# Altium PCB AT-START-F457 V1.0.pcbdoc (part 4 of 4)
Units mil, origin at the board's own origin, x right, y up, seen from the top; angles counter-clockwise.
Board outline 11593.57 x 3554 mil, 2 copper layers (Top Layer, Bottom Layer); 196 components, 231 nets, 905 pads, 932 vias.
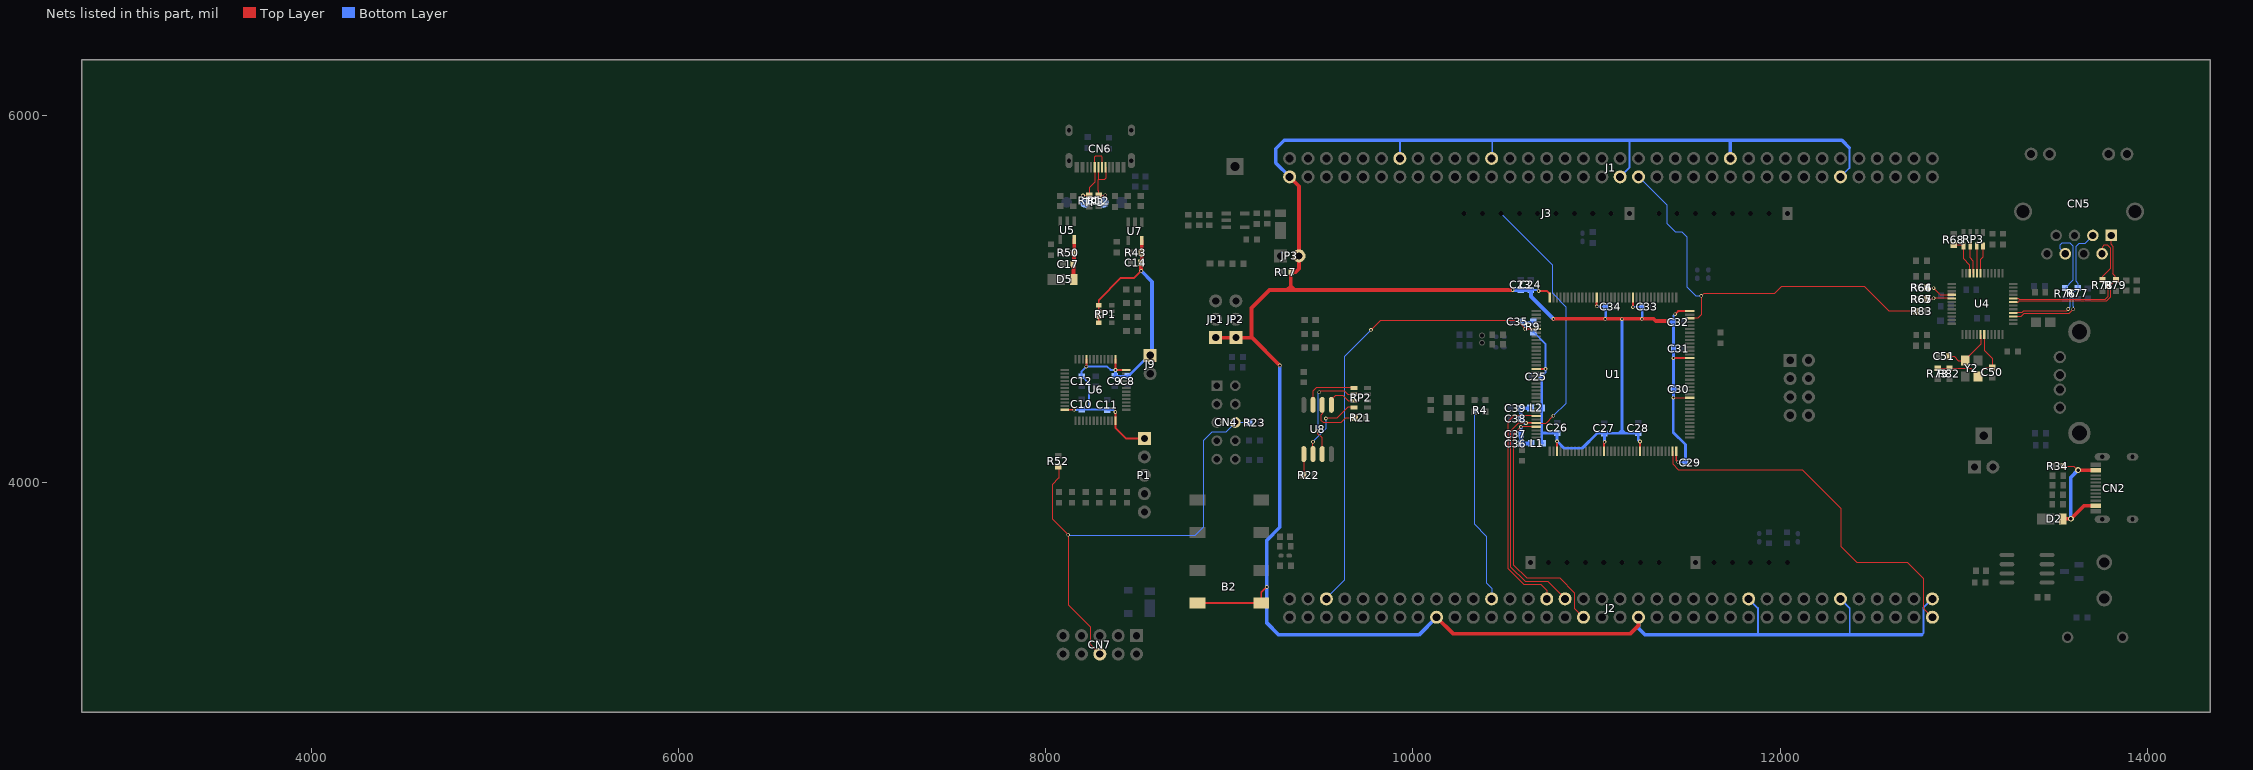
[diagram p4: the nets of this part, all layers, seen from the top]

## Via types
v1: diameter 19.7, hole 11.8, Top Layer to Bottom Layer, 489 vias
v2: diameter 19.68, hole 11.81, Top Layer to Bottom Layer, 425 vias
v3: diameter 31.5, hole 19.68, Top Layer to Bottom Layer, 18 vias

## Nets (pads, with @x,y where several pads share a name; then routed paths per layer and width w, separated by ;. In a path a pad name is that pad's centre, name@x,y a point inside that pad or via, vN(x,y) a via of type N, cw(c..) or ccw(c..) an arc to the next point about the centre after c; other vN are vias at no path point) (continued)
PH1_E: J2.24 R4.1 | length 1063.9
  Bottom Layer w6: R4.1@10335.06,4391.98 10335.06,3775.08 10401.16,3708.98 10401.16,3453.88 10429.16,3425.88 J2.24@10429.17,3367.08
PH2: J1.34 R83.1 U1.106 | length 2247.6
  Top Layer w6: U1.106@11508.56,4895.08 11551.03,4895.08 11570.59,4914.64 v2(11570.59,5017.3) 11583,5029.71 11969.32,5029.71 12005.63,5066.03 12461.73,5066.03 12594.18,4933.58 R83.1@12741.42,4933.58
  Bottom Layer w6: J1.34@11229.16,5665.68 11230.56,5665.68 11381.86,5514.38 11381.86,5413.88 11428.36,5367.38 11463.36,5367.38 11491.76,5338.98 11491.76,5065.69 11540.15,5017.3 v2(11570.59,5017.3)
PH3: J2.71 U1.71 | length 2046.3
  Top Layer w6: U1.71@11415.06,4171.68 11415.06,4101.68 11446.53,4070.32 12121.41,4070.32 12331.21,3860.53 12331.21,3654.73 12418.36,3567.58 12692.66,3567.58 12780.26,3479.88 12780.26,3316.08 J2.71@12829.17,3267.08
PH4: J2.30 U1.30 | length 1275.9
  Top Layer w6: U1.30@10671.86,4363.61 10548.56,4363.61 10515.57,4330.61 10515.57,3534.61 10603.57,3446.61 10695.57,3446.61 10729.17,3413.01 J2.30@10729.17,3367.08
QSPI1_CS: R22.2 U8.1 | length 116
  Top Layer w6: R22.2@9405.96,4039.98 9406.16,4040.18 U8.1@9406.16,4155.92
QSPI1_IO0: RP2.7 U8.5 | length 176.4
  Top Layer w6: U8.5@9556.16,4423.64 9556.16,4453.17 9579.6,4476.61 9617.57,4476.61 9648.91,4445.28 RP2.7@9680.35,4445.28
QSPI1_IO1: RP2.8 U8.2 | length 401.8
  Top Layer w5.98: U8.2@9456.16,4155.92 v2(9456.18,4222.41)
  Top Layer w6: v2(9526.59,4349.49) 9586.44,4349.49 9646.8,4409.85 RP2.8@9680.35,4409.85 ccw(c9680.11,4409.6) RP2.8@9680.11,4409.95
  Bottom Layer w6: v2(9456.18,4222.41) 9456.18,4223.22 9526.59,4293.63 v2(9526.59,4349.49)
QSPI1_IO2: RP2.6 U8.3 | length 552.2
  Top Layer w5.98: v2(9482.61,4281.14) 9482.61,4267.58 9506.16,4244.03 U8.3@9506.16,4155.92
  Top Layer w6: v2(9489.97,4492.3) 9498.29,4500.61 9625.57,4500.61 9645.47,4480.72 RP2.6@9680.35,4480.72
  Bottom Layer w5.98: v2(9482.61,4281.14) 9481.57,4282.18 9481.57,4483.9 v2(9489.97,4492.3)
QSPI1_IO3: RP2.5 U8.7 | length 307.3
  Top Layer w6: U8.7@9455.57,4424.23 ccw(c9456.18,4424.23) U8.7@9456.16,4423.64 ; U8.7@9455.56,4424.28 9455.56,4498.6 9473.1,4516.15 RP2.5@9680.35,4516.15
QSPI1_SCK: R21.2 U8.6 | length 287.1
  Top Layer w6: U8.6@9506.16,4423.64 9506.16,4374.87 9499.57,4368.29 9499.57,4340.61 9511.57,4328.61 9609.57,4328.61 9634.8,4353.85 R21.2@9685.52,4353.85
REF_CLK: R68.2 RP3.5 U4.22 | length 218.5
  Top Layer w6: R68.2@12946.16,5296.48 12992.56,5296.48 12999.96,5289.18 12999.96,5218.28 13033.36,5184.88 U4.22@13033.36,5141.28
RX+: CN5.3 R77.2 U4.3 | length 822.4
  Top Layer w6: U4.3@13269.53,4905.07 13312.69,4905.07 13330.49,4922.87 13575.43,4922.87 v2(13597.03,4944.47)
  Bottom Layer w6: v2(13597.03,4944.47) 13597.03,4960.96 13593.54,4964.44 13593.54,5031.86 13622.25,5060.58 13622.25,5085.93 13609.51,5098.66 13609.51,5285.42 13625.67,5301.58 13658.26,5301.58 CN5.3@13703.26,5346.48
RX-: CN5.6 R76.2 U4.4 | length 829.2
  Top Layer w6: U4.4@13269.53,4924.76 13315.43,4924.76 13325.52,4934.85 13558.95,4934.85 v2(13569.76,4945.66)
  Bottom Layer w6: R76.2@13552.21,5059.63 13552.58,5059.63 13597.51,5104.56 13597.51,5287.18 13580.75,5303.94 13533.87,5303.94 13523.23,5293.3 13523.23,5276.71 CN5.6@13553.46,5246.48 ; R76.2@13552.26,5057.48 13581.54,5028.2 13581.54,4957.44 v2(13569.76,4945.66)
RXD0: R65.2 R67.2 U4.29 | length 173.3
  Top Layer w6: R65.2@12800.74,4998.98 12828.39,4998.98 12832.9,5003.5 U4.29@12934.89,5003.5
  Bottom Layer w6: R67.2@12801.14,4998.59 12830.58,4998.59 v2(12836.09,5004.1)
RXD1: R64.2 R66.2 U4.28 | length 186.7
  Top Layer w6: R64.2@12800.74,5062.81 12833.73,5062.81 12873.36,5023.18 U4.28@12934.89,5023.18
  Bottom Layer w6: R66.2@12800.51,5060.32 12835.3,5060.32 v2(12836.27,5059.35)
SWO: CN4.6 CN7.6 R23.1 R52.2 | length 2661.3
  Top Layer w6: 8070.23,4023.63 8035.17,3988.57 8035.17,3804.01 v2(8122.8,3716.38) 8124.77,3714.41 8124.77,3332.21 8245.21,3211.77 8245.21,3116.85 CN7.6@8295.43,3066.63 ; 8070.26,4023.68 R52.2@8070.26,4081.58
  Bottom Layer w6: v2(8122.8,3716.38) 8124.56,3714.61 8815.89,3714.61 8860.26,3758.98 8860.26,4231.98 8906.26,4277.98 8984.36,4277.98 9034.56,4328.18 9112.76,4328.18 R23.1@9112.76,4325.98
TX+: CN5.1 R79.2 U4.7 | length 899.7
  Top Layer w6: U4.7@13269.59,4983.81 13295.94,4983.81 13299.69,4987.56 13775.42,4987.56 13798.24,5010.38 13798.24,5073.37 13826.16,5101.38 13826.16,5123.08 13812.82,5136.48 13812.82,5287.18 13799.82,5300.18 13799.82,5334.47 13803.46,5338.12 CN5.1@13803.46,5346.48
TX-: CN5.2 R78.2 U4.8 | length 906.6
  Top Layer w6: U4.8@13269.53,5003.5 13298.2,5003.5 13302.15,4999.56 13770.45,4999.56 13786.24,5015.35 13786.24,5069.2 R78.2@13755.66,5099.78 ; CN5.2@13753.46,5246.48 13753.46,5283.19 13761.99,5291.72 13784.84,5291.72 13800.82,5275.75 13800.82,5168.62 13756.08,5123.88 R78.2@13756.08,5103.9
TXD0: RP3.7 U4.20 | length 148.7
  Top Layer w6: RP3.7@13070.76,5289.18 13072.66,5287.28 U4.20@13072.68,5141.29
TXD1: RP3.8 U4.19 | length 153.7
  Top Layer w6: U4.19@13092.37,5141.29 13092.36,5216.08 13106.26,5229.98 RP3.8@13106.26,5289.18
TXEN: RP3.6 U4.21 | length 155.2
  Top Layer w6: RP3.6@13035.36,5289.18 13035.36,5224.88 13052.96,5207.18 U4.21@13053,5141.29
USBM: CN6.A7 CN6.B7 R12.1 TP3.2 | length 334.9
  Top Layer w6: CN6.A7@8287.41,5717.9 8287.41,5649.64 ; v2(8324.77,5565.01) 8324.24,5564.48 R12.1@8290.08,5564.48 8290.08,5586.36 8287.41,5589.03 8287.41,5649.64 ; CN6.B7@8326.71,5717.9 8326.71,5657.74 8318.61,5649.64 8287.41,5649.64
  Bottom Layer w6: TP3.2@8314.58,5526.61 8324.77,5536.8 v2(8324.77,5565.01)
USBP: CN6.A6 CN6.B6 R11.1 TP3.3 | length 398.8
  Top Layer w6: v2(8203.57,5563.81) 8203.69,5563.69 R11.1@8238.07,5563.69 8238.07,5607.32 8267.71,5636.95 CN6.B6@8267.71,5717.9 8267.71,5774.07 8272.74,5779.1 8302.29,5779.1 8307.01,5774.39 CN6.A6@8307.01,5717.9
  Bottom Layer w6: v2(8203.57,5563.81) 8203.57,5537.62 TP3.3@8214.58,5526.61
VBAT: C35.1 J2.6 R9.1 U1.6 | length 2722.4
  Top Layer w6: v2(9772.21,4831.97) 9821.36,4881.18 10566.96,4881.18 v2(10611.21,4836.97) 10612.06,4836.08 U1.6@10671.86,4836.08
  Top Layer w10: v2(10611.21,4836.97) U1.6@10671.86,4836.08
  Bottom Layer w6: J2.6@9529.17,3367.08 9529.16,3370.98 9628.26,3470.08 9628.26,4687.98 v2(9772.21,4831.97) ; C35.1@10598.77,4875.97 10654.76,4875.98 R9.1@10655.26,4875.48
  Bottom Layer w10: v2(10611.21,4836.97) 10611.16,4863.48 10598.66,4875.98 R9.1@10655.16,4875.48
VBUS: CN2.A4B9 CN2.B4A9 D2.2 R34.2 | length 676.4
  Top Layer w6: R34.2@13542.43,4090.63 13600.62,4090.63 v3(13622.88,4068.37)
  Top Layer w20: D2.2@13539.49,3802.96 13539.6,3803.07 v3(13583.83,3803.07) 13654.99,3874.23 CN2.A4B9@13718.81,3874.23 ; v3(13622.88,4068.37) 13624.02,4067.23 CN2.B4A9@13718.81,4067.23
  Bottom Layer w20: v3(13583.83,3803.07) 13583.83,4029.31 v3(13622.88,4068.37)
VCC: C8.2 C9.2 C10.2 C11.2 C12.2 C14.2 J9.1 P1.1 R43.1 RP1.1 RP1.2 RP1.3 RP1.4 U6.1 U6.9 U6.24 U6.36 U6.48 U7.5 | length 2489.8
  Top Layer w10: U6.24@8104.56,4397.08 8154.68,4397.08 v2(8155.18,4396.59) ; v2(8221.57,4631.81) 8222.69,4632.94 U6.9@8222.69,4672.63 ; RP1.4@8289.33,4870.97 RP1.3@8289.33,4902.46 RP1.2@8289.33,4933.96 RP1.1@8289.33,4965.45 8289.33,4994.38 8409.97,5115.01 8482.37,5115.01 v2(8520.77,5153.41) ; v2(8379.97,4385.01) 8380.17,4384.81 U6.36@8380.17,4337.98 8380.16,4298.64 8438.61,4240.18 P1.1@8538.16,4240.18 ; U6.1@8380.16,4672.68 8380.16,4632.38 8380.46,4632.08 v2(8380.46,4613.78) 8400.16,4613.78 8400.36,4613.58 U6.48@8439.26,4613.58
  Top Layer w20: v2(8520.77,5153.41) 8519.37,5154.82 C14.2@8519.37,5197.16 8524.34,5202.13 U7.5@8524.34,5318.39
  Bottom Layer w6: C10.2@8196.77,4398.65 C10.2@8198.74,4398.65
  Bottom Layer w10: v2(8155.18,4396.59) 8170.98,4396.59 8173.05,4398.65 C10.2@8196.77,4398.65 ; C10.2@8198.74,4398.65 8235.87,4398.65 ; v2(8379.97,4385.01) 8369.13,4395.85 C11.2@8335.17,4395.85 8332.01,4399.01 8299.97,4399.01 8299.61,4398.65 8235.87,4398.65 ; v2(8380.46,4613.78) 8353.6,4613.78 8335.57,4631.81 v2(8221.57,4631.81) 8196.37,4606.61 C12.2@8196.37,4579.77 8198.34,4579.77 8235.57,4542.54 8235.57,4398.95 8235.87,4398.65
  Bottom Layer w15: v2(8380.46,4613.78) 8380.46,4584.26 C9.2@8376.37,4580.17 8445.57,4580.17 C8.2@8446.37,4580.97 8450.73,4580.97 8563.33,4693.58 J9.1@8569.46,4693.58
  Bottom Layer w20: v2(8520.77,5153.41) 8579.57,5094.61 8579.57,4703.69 J9.1@8569.46,4693.58
VCC3.5V: C17.2 D5.2 R50.1 U5.5 | length 217
  Top Layer w20: D5.2@8152.36,5107.05 U5.5@8155.56,5324.05
VDD: B2.1 B2.3 C23.1 C24.1 C25.1 C26.1 C27.1 C28.1 C29.1 C30.1 C31.1 C32.1 C33.1 C34.1 J1.12 J1.23 J1.36 J1.49 J1.59 J1.72 J2.17 J2.39 J2.52 J2.62 J2.72 JP1.1 JP2.1 JP3.2 L1.1 L2.1 R9.2 R17.2 U1.17 U1.39 U1.52 U1.62 U1.72 U1.84 U1.95 U1.108 U1.121 U1.131 U1.144 | length 18151.8
  Top Layer w6: v2(11001.21,4959.97) 11001.16,5007.88 U1.131@11001.66,5008.28 ; v2@11198.26,4955.98 11198.26,5007.98 U1.121@11198.46,5008.28 ; v2(11237.21,4223.97) 11237.86,4223.28 U1.62@11237.86,4171.68 ; v2(11419.26,4462.98) 11420.26,4461.98 11508.36,4461.98 U1.84@11508.56,4461.98
  Top Layer w10: B2.3@8828.03,3344.39 B2.1@9174.49,3344.39 9174.46,3402.18 v2@9204.26,3431.98 ; U1.17@10671.86,4619.52 v2(10722.29,4619.56) ; v2(10685.21,5043.97) 10730.21,5043.97 10745.68,5028.51 U1.144@10745.68,5008.31 ; U1.39@10785.06,4171.68 v2(10785.09,4224.97) ; v2(11001.21,4959.97) U1.131@11001.66,5008.28 ; U1.52@11040.96,4171.68 11040.96,4218.78 v2@11044.26,4221.98 ; v2@11198.26,4955.98 U1.121@11198.46,5008.28 ; v2(11237.21,4223.97) U1.62@11237.86,4171.68 ; v2(11419.26,4678.58) U1.95@11508.48,4678.57 ; v2(11428.26,4917.98) 11444.76,4934.48 U1.108@11508.48,4934.48 ; U1.72@11434.66,4171.68 11434.66,4121.17 v2(11444.88,4110.95) ; U1.84@11508.36,4461.98 U1.84@11508.46,4462.08
  Top Layer w20: JP1.1@8926.26,4789.98 9036.26,4789.98 9121.56,4789.98 ; v2(9275.08,4638.41) 9123.56,4789.98 9121.56,4789.98 ; J1.72@9329.18,5665.65 9380.21,5614.62 JP3.2@9380.21,5234.97 ; JP3.2@9380.21,5234.97 9380.16,5164.98 9362.26,5146.98 9335.76,5146.98 9335.86,5070.28 ; J2.17@10129.17,3267.08 10218.28,3177.97 11185.21,3177.97 11229.18,3221.93 J2.39@11229.17,3267.08 ; v2@10543.26,5048.98 9357.26,5048.98 ; v2(10765.65,4891.76) 10765.87,4891.98 v2@11048.26,4891.98 ; v2(11048.21,4891.97) v2(11247.21,4891.97) 11312.67,4891.97 11323.77,4880.87 v1(11387.81,4880.87) ; 9121.56,4789.98 9121.56,4951.28 9219.26,5048.98 9315.36,5048.98 ; 9315.36,5048.98 9335.86,5070.28 ; 9315.36,5048.98 9357.26,5048.98 ; 9335.86,5070.28 9357.26,5048.98
  Bottom Layer w6: v2(11001.21,4959.97) v2@11002.16,4958.98 ; C32.1@11418.02,4872.73 C32.1@11418.02,4879.87
  Bottom Layer w10: J1.59@9929.18,5765.65 9929.18,5862.18 9931.37,5864.38 ; J1.49@10429.18,5765.65 10432.2,5768.67 10432.2,5864.38 ; C24.1@10643.21,5049.41 10679.77,5049.41 v2(10685.21,5043.97) ; R9.2@10655.16,4820.48 10658.06,4820.48 10722.26,4756.28 v2(10722.29,4619.56) ; C25.1@10700.77,4576.97 10701.87,4578.07 10722.29,4598.48 v2(10722.29,4619.56) ; v2@11001.16,4958.98 11002.16,4958.98 C34.1@11050.76,4958.98 ; J1.36@11129.18,5665.65 11179.27,5715.74 11179.27,5864.38 ; v2@11198.26,4955.98 11200.16,4957.98 C33.1@11249.65,4957.97 ; C32.1@11419.02,4880.87 11419.02,4908.74 v2(11428.26,4917.98) ; C30.1@11420.01,4508.61 11422.36,4510.97 C30.1@11431.65,4510.97 ; v2(11444.88,4110.95) 11482.5,4110.95 C29.1@11484.44,4109.02 ; J2.52@11829.17,3367.08 11879.21,3317.04 11879.21,3170.98 ; J2.62@12329.17,3367.08 12379.21,3317.04 12379.21,3170.98 ; J1.12@12329.18,5665.65 12377.21,5713.68 12377.21,5823.97 ; 12771.26,3170.98 12780.26,3179.98 12780.26,3318.08 J2.72@12829.17,3367.08
  Bottom Layer w15: C25.1@10701.87,4578.07 L2.1@10701.88,4406.61 10701.87,4270.79 10701.56,4270.48 ; L1.1@10705.57,4214.98 10701.56,4218.98 10701.56,4270.48 ; C27.1@11043.26,4268.48 11003.66,4268.48 10922.88,4187.61 10823.59,4187.61 10785.06,4226.01 10785.26,4270.48 10701.56,4270.48 ; C27.1@11043.26,4269.48 11122.36,4269.48 ; v2@11044.26,4221.98 C27.1@11044.26,4267.48 ; v2@11048.26,4891.98 11050.76,4891.98 C34.1@11050.76,4958.98 ; 11138.66,4285.98 11122.36,4269.48 ; v2(11138.7,4890.97) 11138.7,4285.98 11155.2,4269.48 ; v2@11237.26,4223.98 11228.26,4232.98 11228.26,4269.48 11155.2,4269.48 ; v2(11247.21,4891.97) 11249.66,4894.48 C33.1@11249.65,4957.97 ; v2@11418.01,4454.73 11418.01,4273.17 11484.44,4206.75 C29.1@11484.44,4109.02 ; v2@11420.01,4462.77 C30.1@11420.01,4508.61 C32.1@11420.01,4872.61 ; 11122.36,4269.48 11155.2,4269.48
  Bottom Layer w20: v2(9275.08,4638.41) 9275.08,3756.83 9205.26,3687.01 9205.26,3235.98 9270.26,3170.98 10033.06,3170.98 J2.17@10129.17,3267.08 ; J1.72@9329.16,5665.68 9253.46,5741.38 9253.46,5818.28 9299.56,5864.38 9931.37,5864.38 10432.2,5864.38 11179.27,5864.38 11729.18,5864.38 ; v2(10543.21,5048.97) 10587.57,5048.97 10642.77,5048.97 C24.1@10643.21,5049.41 10643.21,5014.2 v2(10765.65,4891.76) ; J2.39@11229.17,3267.08 11231.21,3265.04 11231.21,3204.97 11265.2,3170.98 11879.21,3170.98 12379.21,3170.98 12771.26,3170.98 ; v1(11387.81,4880.87) C32.1@11418.01,4880.87 ; J1.23@11729.18,5765.65 11729.18,5864.38 ; 12377.26,5823.98 12336.76,5864.38 11729.18,5864.38
  other v2: 9204.21,3431.97 11044.21,4221.97 11198.21,4955.97
VDDA: C36.1 C37.1 J2.33 L1.2 U1.33 | length 1590.7
  Top Layer w6: U1.33@10671.86,4304.56 10588.86,4304.58 10548.16,4263.88 10548.16,3552.03 10619.2,3480.98 10799.46,3480.98 10880.26,3400.18 10880.26,3316.08 J2.33@10929.17,3267.08
  Bottom Layer w6: v2@10588.26,4303.98 10588.66,4303.48 C37.1@10588.66,4264.98 ; L1.2@10642.86,4212.98 L1.2@10644.94,4214.98
  Bottom Layer w20: v2@10588.26,4303.98 10588.66,4264.98 10588.66,4212.98 L1.2@10642.86,4212.98 ; L1.2@10642.96,4212.98 L1.2@10644.96,4214.98
  other v2: 10588.21,4303.97
VREF+: C38.1 C39.1 J2.32 J3.8 L2.2 U1.32 | length 2918.4
  Top Layer w6: v2(10616.21,4324.97) 10671.16,4324.98 U1.32@10671.86,4324.24 ; v2@10765.66,4363.98 10725.86,4324.18 U1.32@10671.86,4324.24 ; J2.32@10829.17,3367.08 10734.26,3461.98 10612.2,3461.98 10531.56,3542.63 10531.56,4281.28 10574.46,4324.18 U1.32@10671.86,4324.24
  Bottom Layer w6: J3.8@10479.86,5465.98 10758.26,5187.58 10758.26,5033.65 10832.57,4959.34 10832.57,4430.89 v2@10765.66,4363.98 ; C39.1@10586.77,4404.97 10586.76,4348.98 C38.1@10587.13,4348.61 ; L2.2@10639.53,4404.98 L2.2@10641.25,4406.61
  Bottom Layer w20: v2(10616.21,4324.97) 10610.76,4324.98 C38.1@10587.13,4348.61 10587.12,4404.62 C39.1@10586.77,4404.97 L2.2@10639.53,4404.98 ; L2.2@10639.63,4404.98 L2.2@10641.27,4406.61
  other v2: 10765.63,4364
XT1: C50.1 R73.2 R82.1 U4.43 Y2.1 | length 539.8
  Top Layer w6: R73.2@12858.77,4623.47 12921.57,4623.47 R82.1@12922.37,4622.67 13037.11,4622.67 13072.02,4587.76 Y2.1@13072.02,4583.64 ; Y2.1@13077.62,4578.5 13077.16,4578.5 Y2.1@13072.02,4583.64 ; U4.43@13112.05,4806.65 13112.05,4721.74 13156.37,4677.41 C50.1@13156.37,4627.77 13121.93,4627.77 13077.8,4583.64 Y2.1@13072.02,4583.64
XT2: C51.1 U4.42 Y2.3 | length 273.7
  Top Layer w6: C51.1@12920.73,4688.21 12948.37,4688.21 12971.46,4665.12 Y2.3@13008.72,4665.12 13008.72,4669.36 13092.37,4753.01 U4.42@13092.37,4806.65
pads on no net: CN2.A8 CN2.B8 CN5.7 CN6.A8 CN6.B8 J4.1 J4.8 U4.11 U4.14 U4.16 U4.17 U4.18 U4.26 U4.27 U4.34 U4.35 U4.38 U4.39 U4.45 U6.2 U6.3 U6.4 U6.5 U6.6 U6.14 U6.15 U6.16 U6.17 U6.18 U6.21 U6.22 U6.29 U6.38 U6.41 U6.42 U6.43 U6.45 U6.46

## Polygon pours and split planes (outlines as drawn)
GND on Top Layer (solid, remove dead copper, pour order 0): 7929.57,6050.61 14093.57,6050.61 14093.57,3000.61 7929.57,3000.61
GND on Bottom Layer (solid, remove dead copper, pour order 2): 7904.5,6054 14034.5,6054 14034.5,3000 7904.5,3000

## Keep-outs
Top Layer:
  region: 8093.57,6044.61 8503.57,6044.61 8503.57,5692.61 8093.57,5692.61
  region: 11000.57,5092.61 11028.57,5092.61 11028.57,5089.61 11000.57,5089.61
  region: 8427.33,4456.25 8427.33,4435.51 8454.37,4435.51 8454.37,4456.25 8427.4,4456.25
  region: 13170.22,4819.74 13170.22,4788.69 13192.59,4788.69 13192.59,4819.72 13170.85,4819.72
  region: 13239.55,4969.43 13239.55,4938.7 13245.85,4938.7 13311.65,4938.7 13311.65,4944.48 13311.65,4969.43 13240.73,4969.43
  region: 9705.37,4533.67 9727.83,4533.67 9727.83,4528.15 9705.37,4528.15
Bottom Layer:
  region: 14037.21,5173.97 13269.21,5173.97 13269.21,6033.97 14037.21,6033.97
Board Outline Layer:
  circle w1: c12139.81,4865.97 r62.99
  circle w10: c12139.81,4865.97 r62.99
  circle w1: c10139.81,5465.96 r62.99
  circle w10: c10139.81,5465.96 r62.99
  circle w1: c10089.81,3565.97 r62.99
  circle w10: c10089.81,3565.97 r62.99
  circle w1: c8818.39,5874.63 r62.99
  circle w10: c8818.39,5874.63 r62.99
  circle w1: c8818.39,3158.09 r62.99
  circle w10: c8818.39,3158.09 r62.99
  circle w1: c13109.73,3158.09 r62.99
  circle w10: c13109.73,3158.09 r62.99
  circle w1: c13109.73,5874.63 r62.99
  circle w10: c13109.73,5874.63 r62.99
  region: 14037.21,5161.97 13269.21,5161.97 13269.21,6033.97 14037.21,6033.97
  lines w8: 8582.96,6032.21 cw(c8582.96,5953.47) 8661.7,5953.47 8661.7,5631.63 8701.21,5631.63 8701.21,5953.46 cw(c8779.95,5953.46) 8779.95,6032.2 ; 8583.39,3000.61 ccw(c8583.39,3079.35) 8662.13,3079.35 8662.16,3079.38 8662.16,3518.58 8700.96,3518.58 8700.96,3079.38 8700.96,3079.35 ccw(c8779.7,3079.35) 8779.7,3000.61 ; 8661.66,5546.58 8661.66,5553.58 8701.26,5553.58 8701.26,5546.58 8701.22,5546.58 8701.22,5224.75 8701.22,4903.97 ; 8661.7,5546.59 8661.7,5224.75 8661.7,4904.49 ; 8661.7,4904.49 8662.57,4903.61 ; 8661.7,4904.49 ccw(c8662.57,4904.49) 8662.57,4903.61 ; 8662.57,4903.61 8700.86,4903.61 ; 8700.86,4903.61 8701.22,4903.97 ; 8700.86,4903.61 ccw(c8700.86,4903.97) 8701.22,4903.97 ; 8661.57,3606.61 8661.57,3698.61 8701.57,3698.61 8701.57,3606.61 8661.57,3606.61 ; 8661.57,3810.61 8661.57,4809.61 8661.57,4825.61 8680.57,4825.61 8700.57,4825.61 8700.57,3825.61 8700.57,3810.61 8699.57,3810.61 8661.57,3810.61
  lines w10: 7929.57,3079.35 ccw(c8008.31,3079.35) 8008.31,3000.61 13953.19,3000.61 ccw(c13953.19,3079.35) 14031.93,3079.35 14031.93,5953.37 ccw(c13953.19,5953.37) 13953.19,6032.11 8008.31,6032.11 ccw(c8008.31,5953.37) 7929.57,5953.37 7929.57,3079.35

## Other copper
Top Layer:
  drawing of 1092 lines, arcs and shapes, not listed
Bottom Layer:
  drawing of 655 lines, arcs and shapes, not listed

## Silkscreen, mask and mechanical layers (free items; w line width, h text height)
Top Silkscreen Layer:
  region: 12061.06,5334.85 12023.06,5334.85 12043.06,5354.85 12063.06,5334.85
  region: 11922.7,5352.85 11960.7,5352.85 11940.7,5332.85 11920.7,5352.85
  lines w6: 8141.98,3304.61 8141.98,3603.61 ; 8238.38,3304.61 8238.38,3603.61 ; 8334.77,3303.61 8334.77,3603.61 ; 8431.17,3309.61 8431.17,3603.61
  lines w8: 8243,3218.63 8243,3258.63 8343,3258.63 8343,3217.63 ; 8533.55,3272.63 8496.55,3235.63 8457.55,3274.63 8533.55,3274.63 ; 8842.11,4558.1 8875.56,4528.18 8841.33,4499.39 8841.33,4557.7 8842.9,4557.31 ; 8881.91,4376.46 8859.05,4376.46 8859.05,4277.18 8882.06,4277.18 8882.06,4278.37
  lines w10: 10652.7,5212.76 12068.4,5212.76 ; 10942.92,3858.17 11395.93,3858.17 ; 11541.16,3858.17 12101.16,3858.17
  text "143" at 9294.03,5925.4 h53.08
  text "133" at 9778.67,5925.4 h53.08
  text "123" at 10283.4,5925.34 h53.08
  text "113" at 10800.72,5925.42 h53.08
  text "103" at 11286.94,5925.43 h53.08
  text "93" at 11797.25,5925.41 h53.08
  text "83" at 12303.16,5925.43 h53.08
  text "73" at 12798.04,5925.41 h53.08
  text "D8" at 12614.84,5826.64 h53.08 r45
  text "B12" at 12814.13,5827.4 h53.08 r45
  text "E0" at 9430.12,5824.52 h53.08 r45
  text "D7" at 10318.9,5825.28 h53.08 r45
  text "D12" at 12415.09,5824.62 h53.08 r45
  text "D10" at 12514.89,5825.31 h53.08 r45
  text "B14" at 12714.99,5825.34 h53.08 r45
  text "B8" at 9526.51,5823.55 h53.08 r45
  text "B3" at 9826.63,5823.87 h53.08 r45
  text "D1" at 10725.32,5823.89 h53.08 r45
  text "A14" at 11016.9,5823.66 h53.08 r45
  text "A13" at 11214.65,5823.89 h53.08 r45
  text "A11*" at 11319.48,5823.92 h53.08 r45
  text "A9" at 11426.06,5823.63 h53.08 r45
  text "D14" at 12219.86,5823.66 h53.08 r45
  text "B5" at 9727.99,5823.17 h53.08 r45
  text "D5" at 10530.89,5822.21 h53.08 r45
  text "D3" at 10626.84,5822.42 h53.08 r45
  text "B7" at 9625.2,5820.13 h53.08 r45
  text "G10" at 10218.23,5820.36 h53.08 r45
  text "G8" at 11820.07,5819.93 h53.08 r45
  text "G12" at 10118.32,5818.91 h53.08 r45
  text "GND" at 11114.44,5819.33 h53.08 r45
  text "G2" at 12119.89,5819.18 h53.08 r45
  text "GND" at 9334.9,5817.96 h53.08 r45
  text "C7" at 11625.79,5817.66 h53.08 r45
  text "G6" at 11922.73,5818.3 h53.08 r45
  text "C12" at 10818.19,5816.54 h53.08 r45
  text "C9" at 11519.64,5817.36 h53.08 r45
  text "G4" at 12017.33,5817.43 h53.08 r45
  text "GND" at 12312.34,5817.24 h53.08 r45
  text "G14" at 10017.34,5816.49 h53.08 r45
  text "VDD" at 10418.16,5815.77 h53.08 r45
  text "C10" at 10920.36,5815.82 h53.08 r45
  text "VDD" at 11710.07,5815.74 h53.08 r45
  text "VDD" at 9913.84,5812.5 h53.08 r45
  text "GND" at 8977.64,5808.6 h61.93
  text "Ethernet" at 13283.52,5621.66 h82.58 r90
  text "B6" at 9742.77,5537.36 h53.08 r45
  text "B9" at 9540.12,5533.83 h53.08 r45
  text "E1" at 9435.76,5530.95 h53.08 r45
  text "B4" at 9835.99,5531.15 h53.08 r45
  text "D6" at 10432.23,5530.95 h53.08 r45
  text "G11" at 10230.83,5527.56 h53.08 r45
  text "D4" at 10637.55,5524.86 h53.08 r45
  text "G13" at 10109.58,5524.31 h53.08 r30
  text "G9" at 10324.42,5524.4 h53.08 r45
  text "D0" at 10838.83,5524.06 h53.08 r45
  text "G5" at 12031.09,5523.75 h53.08 r45
  text "G3" at 12133.79,5523.58 h53.08 r45
  text "D2" at 10739.23,5522.71 h53.08 r45
  text "H2" at 11232.67,5523.43 h53.08 r45
  text "C6" at 11737.72,5522.99 h53.08 r45
  text "G7" at 11932.92,5522.76 h53.08 r45
  text "A8*" at 11533.03,5521.69 h53.08 r45
  text "C8" at 11633,5522.25 h53.08 r45
  text "C11" at 10934.3,5519.65 h53.08 r45
  text "A10" at 11429.72,5519.73 h53.08 r45
  text "G15" at 9928.83,5517.95 h53.08 r45
  text "D11" at 12532.33,5516.61 h53.08 r45
  text "A15" at 11025.3,5515.46 h53.08 r45
  text "D15" at 12226.07,5515 h53.08 r45
  text "D9" at 12634.99,5513.64 h53.08 r45
  text "VDD" at 9317.08,5512.52 h53.08 r45
  text "GND" at 11820.45,5513.47 h53.08 r45
  text "GND" at 10021.29,5511.87 h53.08 r45
  text "GND" at 10526.54,5511.97 h53.08 r45
  text "A12*" at 11322.84,5511.95 h53.08 r45
  text "B15" at 12734.91,5511.09 h53.08 r45
  text "D13" at 12427.78,5509.01 h53.08 r45
  text "B13" at 12832.59,5509.41 h53.08 r45
  text "VDD" at 11121.07,5507.7 h53.08 r45
  text "VDD" at 12323.24,5503.68 h53.08 r45
  text "BOOT0" at 9597.79,5485.43 h44.24 r45
  text "4" at 11676.82,5362.91 h69.7 r90
  text "8" at 11216.74,5361.97 h69.7 r90
  text "7" at 11379.82,5361.91 h69.7 r90
  text "2" at 11873.82,5361.91 h69.7 r90
  text "13" at 10719.33,5322.2 h70.78 r90
  text "12" at 10819.33,5322.2 h70.78 r90
  text "#6" at 11476.41,5316.14 h70.78 r90
  text "#5" at 11577.41,5316.14 h70.78 r90
  text "#9" at 11120.33,5315.2 h70.78 r90
  text "#3" at 11776.41,5315.14 h70.78 r90
  text "#11" at 10920.62,5295.36 h70.78 r90
  text "#10" at 11019.98,5289.01 h70.78 r90
  text "GND" at 10621.15,5268.8 h70.78 r90
  text "SCL" at 10315.33,5266.66 h70.78 r90
  text "SDA" at 10415.33,5266.66 h70.78 r90
  text "RX 0" at 12081.98,5235.78 h70.78 r90
  text "TX 1" at 11978.75,5234.59 h70.78 r90
  text "DIGITAL(#=PWM)" at 11091.16,5233.28 h61.93
  text "AREF" at 10519.33,5230.13 h70.78 r90
  text "IDD" at 9470.36,5181.95 h88.47
  text "LD:" at 8563.5,5173.13 h72 r270
  text "1" at 8564.8,5059.26 h72 r270
  text "BOOT0" at 8780.66,5046.26 h61.93
  text "BOOT1" at 9002.5,5046.34 h61.93
  text "AT-Link-EZ V1.4" at 7962.83,5043.28 h88.47 r270
  text "2" at 8564.01,4994.65 h72 r270
  text "GND" at 9102.99,4961.2 h61.93
  text "GND" at 8752.93,4958.23 h61.93
  text "3" at 8562.83,4916.24 h72 r270
  text "4" at 8563.62,4842.17 h72 r270
  text "HOST" at 13790.49,4808.32 h80
  text "VDD" at 9107.84,4761.9 h53.08
  text "VDD" at 8764.81,4752.09 h53.08
  text "MISO" at 11855.88,4637.16 h61.93
  text "5V" at 12243.86,4635.19 h61.93
  text "MOSI" at 12227.93,4534.8 h61.93
  text "SCK" at 11869.55,4528.11 h61.93
  text "5V" at 9142.77,4499.98 h61.93
  text "3V3" at 8717.21,4492.94 h61.93
  text "NRST" at 11850.76,4434.8 h61.93
  text "GND" at 12225.46,4428.9 h61.93
  text "BOOT0" at 9120.67,4404.83 h60
  text "SWD" at 8723.91,4396.56 h61.93
  text "NSS" at 11871.52,4335.19 h61.93
  text "PB11" at 12230.68,4330.47 h61.93
  text "SWO" at 9124.61,4298.84 h61.93
  text "SWC" at 8720.95,4293.48 h61.93
  text "GND" at 12907.09,4218.99 h61.93
  text "TX" at 9147.1,4197.39 h61.93
  text "NRST" at 8726.32,4195.36 h61.93
  text "DEVICE" at 13746.14,4165.23 h82.58
  text "GND" at 8729.57,4094.61 h61.93
  text "RX" at 9151.43,4089.04 h61.93
  text "AT-Link" at 8853.71,3980.2 h82.58
  text "PA9" at 12969,3961.57 h61.93
  text "VBUS" at 13104.29,3960.65 h61.93
  text "AT-START-F457 V1.0" at 11230.69,3874.31 h120
  text "POWER" at 11194.49,3781.08 h61.93
  text "ANALOG IN" at 11702.36,3781.07 h61.93
  text "CAN" at 13849.57,3675.61 h82.58
  text "IOREF" at 10781.5,3653.97 h70.78 r90
  text "RESET" at 10876.33,3653.59 h70.78 r90
  text "3.3V" at 10977.33,3651.13 h70.78 r90
  text "GND" at 11178.33,3649.66 h70.78 r90
  text "GND" at 11277.62,3649.66 h70.78 r90
  text "5V" at 11077.33,3648.2 h70.78 r90
  text "AN0" at 11575.41,3646.71 h70.78 r90
  text "AN1" at 11672.34,3646.71 h70.78 r90
  text "AN3" at 11873.28,3644.74 h70.78 r90
  text "AN5" at 12077.37,3644.74 h70.78 r90
  text "AN2" at 11775.17,3643.55 h70.78 r90
  text "AN4" at 11977.29,3643.55 h70.78 r90
  text "3V3" at 8437.43,3599.5 h61.93 r270
  text "RESET" at 8892.74,3598.53 h82.58
  text "SWD" at 8348.38,3597.53 h61.93 r270
  text "SWC" at 8249.49,3594.38 h61.93 r270
  text "GND" at 8063.35,3592.36 h61.93 r270
  text "NRST" at 8151.38,3591.91 h61.93 r270
  text "H" at 14011.16,3536.6 h82.58 r90
  text "F0" at 9717.75,3430.69 h53.08 r45
  text "A2" at 11016.8,3430.92 h53.08 r45
  text "E11" at 12421.2,3431.34 h53.08 r45
  text "E15" at 12625.13,3429.59 h53.08 r45
  text "BOOT0" at 8348.38,3429.49 h61.93 r270
  text "A0" at 10918.4,3429 h53.08 r45
  text "E13" at 12513.82,3428.86 h53.08 r45
  text "F2" at 9822.53,3428.08 h53.08 r45
  text "A4" at 11221.98,3428.26 h53.08 r45
  text "E9" at 12229.37,3428.26 h53.08 r45
  text "SWO" at 8252.64,3426.93 h61.93 r270
  text "E3" at 9317.76,3427.09 h53.08 r45
  text "F4" at 9922.58,3426.55 h53.08 r45
  text "B0" at 11519.56,3426.9 h53.08 r45
  text "F6" at 10118.12,3425.55 h53.08 r45
  text "H1*" at 10420.77,3425.87 h53.08 r45
  text "E5" at 9426.43,3424.75 h53.08 r45
  text "H4" at 10718.04,3425.31 h53.08 r45
  text "B2" at 11620.73,3425.34 h53.08 r45
  text "F12" at 11719.48,3425.46 h53.08 r45
  text "F14" at 11920.05,3424.78 h53.08 r45
  text "B11" at 12722.85,3425.28 h53.08 r45
  text "F10" at 10317.32,3423.73 h53.08 r45
  text "A6" at 11315.47,3424.27 h53.08 r45
  text "E7" at 12126.2,3424.38 h53.08 r45
  text "F8" at 10221.06,3423.09 h53.08 r45
  text "C2" at 10617.79,3423.01 h53.08 r45
  text "G0" at 12024.4,3422.35 h53.08 r45
  text "C0" at 10516.48,3420.09 h53.08 r45
  text "C4" at 11415.99,3420.01 h53.08 r45
  text "VDD" at 12308.18,3419.91 h53.08 r45
  text "C14*" at 9609.03,3418.94 h53.08 r45
  text "VREF+" at 10776.53,3417.68 h44.24 r30
  text "VDD" at 11807.47,3417.75 h53.08 r45
  text "VBAT" at 9504.82,3417.02 h53.08 r45
  text "GND" at 11114.96,3417.09 h53.08 r45
  text "GND" at 9999.65,3416.16 h53.08 r30
  text "VDD" at 12809.29,3413.93 h53.08 r45
  text "TX" at 8155.32,3409.69 h61.93 r270
  text "5V" at 8436.64,3406.14 h61.93 r270
  text "RX" at 8062.34,3405.35 h61.93 r270
  text "L" at 14009.57,3365.61 h82.58 r90
  text "USER" at 8908.71,3214.28 h82.58
  text "C1" at 10637.03,3136.76 h53.08 r45
  text "B1" at 11635.5,3133.71 h53.08 r45
  text "G1" at 12137.35,3134.24 h53.08 r45
  text "F5" at 10038.42,3132.15 h53.08 r45
  text "C3" at 10736.94,3132.35 h53.08 r45
  text "F1" at 9841.47,3131.1 h53.08 r45
  text "A5" at 11338.4,3130.12 h53.08 r45
  text "F3" at 9936.58,3128.84 h53.08 r45
  text "E2" at 9335.59,3128.23 h53.08 r45
  text "F9" at 10341.35,3128.11 h53.08 r45
  text "A3" at 11133.89,3128.19 h53.08 r45
  text "C5" at 11536.52,3128.27 h53.08 r45
  text "F11" at 11734.83,3127.56 h53.08 r45
  text "E8" at 12230.09,3128.26 h53.08 r45
  text "A1*" at 11037.09,3127.48 h53.08 r45
  text "A7" at 11433.35,3126.7 h53.08 r45
  text "E6" at 9537.6,3126.18 h53.08 r45
  text "E4" at 9431.84,3125.38 h53.08 r45
  text "F7" at 10243.95,3124.35 h53.08 r45
  text "H0*" at 10427.81,3122.94 h53.08 r45
  text "E12" at 12534.33,3122.98 h53.08 r45
  text "H3" at 12838.3,3122.46 h53.08 r45
  text "F13" at 11935.66,3120.69 h53.08 r45
  text "F15" at 12034.14,3120.52 h53.08 r45
  text "E10" at 12438.37,3120.36 h53.08 r45
  text "E14" at 12639.85,3120.08 h53.08 r45
  text "B10" at 12732.23,3120.34 h53.08 r45
  text "C13" at 9633.25,3116.92 h53.08 r45
  text "GND" at 11820.04,3114.32 h53.08 r45
  text "VDD" at 10122.81,3111.97 h53.08 r45
  text "GND" at 10820.45,3112.48 h53.08 r45
  text "VDD" at 11222.75,3108.88 h53.08 r45
  text "GND" at 12321.19,3109.27 h53.08 r45
  text "C15*" at 9724.16,3107.16 h53.08 r45
  text "NRST" at 10521.19,3084.69 h53.08 r45
  text "VDDA" at 10908.51,3083.8 h53.08 r45
  text "120Ω" at 14014.57,3060.61 h82.58 r90
  text "1" at 9317.99,3057.82 h52.27
  text "11" at 9823.24,3057.36 h53.08
  text "21" at 10313.01,3057.33 h53.08
  text "31" at 10811.82,3057.33 h53.08
  text "41" at 11307.49,3057.3 h53.08
  text "51" at 11803.16,3057.31 h53.08
  text "61" at 12308.67,3057.31 h53.08
  text "71" at 12819.69,3057.36 h53.08
Bottom Silkscreen Layer:
  text "143" at 9380.01,5855.94 h53.08 r45
  text "139" at 9572.01,5854.79 h53.08 r45
  text "135" at 9788.01,5855.36 h53.08 r45
  text "133" at 9892.01,5855.36 h53.08 r45
  text "129" at 10077.34,5854.79 h53.08 r45
  text "125" at 10280.27,5855.36 h53.08 r45
  text "123" at 10380.27,5855.36 h53.08 r45
  text "109" at 11076.34,5854.79 h53.08 r45
  text "105" at 11285.09,5855.36 h53.08 r45
  text "103" at 11377.86,5855.36 h53.08 r45
  text "141" at 9470.68,5853.05 h53.08 r45
  text "137" at 9681.34,5851.89 h53.08 r45
  text "131" at 9985.34,5852.47 h53.08 r45
  text "127" at 10174.68,5851.89 h53.08 r45
  text "121" at 10477.6,5852.47 h53.08 r45
  text "107" at 11178.09,5851.89 h53.08 r45
  text "101" at 11462.19,5852.47 h53.08 r45
  text "119" at 10573.6,5849.58 h53.08 r45
  text "115" at 10774.94,5850.16 h53.08 r45
  text "113" at 10879.34,5850.16 h53.08 r45
  text "95" at 11766.34,5848.85 h53.08 r45
  text "93" at 11868.48,5848.85 h53.08 r45
  text "85" at 12261.98,5848.85 h53.08 r45
  text "83" at 12369.39,5848.85 h53.08 r45
  text "99" at 11564.48,5848.28 h53.08 r45
  text "89" at 12065.53,5848.28 h53.08 r45
  text "117" at 10674.94,5846.69 h53.08 r45
  text "111" at 10967.34,5847.26 h53.08 r45
  text "79" at 12565.52,5846.54 h53.08 r45
  text "75" at 12767.44,5847.12 h53.08 r45
  text "73" at 12867.15,5847.12 h53.08 r45
  text "91" at 11959.39,5845.96 h53.08 r45
  text "81" at 12466.24,5845.96 h53.08 r45
  text "97" at 11660.48,5845.38 h53.08 r45
  text "87" at 12163.91,5845.38 h53.08 r45
  text "77" at 12665.72,5843.65 h53.08 r45
  text "142" at 9474.68,5579.59 h53.08 r45
  text "132" at 9978.68,5579.01 h53.08 r45
  text "122" at 10468.27,5579.01 h53.08 r45
  text "102" at 11480.29,5579.01 h53.08 r45
  text "144" at 9369.93,5577.28 h53.08 r45
  text "140" at 9576.01,5577.28 h53.08 r45
  text "138" at 9677.34,5577.28 h53.08 r45
  text "134" at 9881.34,5576.7 h53.08 r45
  text "130" at 10070.68,5576.7 h53.08 r45
  text "128" at 10176.01,5577.28 h53.08 r45
  text "124" at 10373.6,5576.7 h53.08 r45
  text "120" at 10580.27,5576.7 h53.08 r45
  text "108" at 11175.34,5577.28 h53.08 r45
  text "104" at 11373.53,5576.7 h53.08 r45
  text "100" at 11574.86,5576.7 h53.08 r45
  text "136" at 9785.34,5576.12 h53.08 r45
  text "126" at 10276.27,5576.12 h53.08 r45
  text "106" at 11265.09,5576.12 h53.08 r45
  text "112" at 10967.01,5573.81 h53.08 r45
  text "118" at 10672.27,5572.07 h53.08 r45
  text "92" at 11965.2,5572.5 h53.08 r45
  text "82" at 12469.15,5572.5 h53.08 r45
  text "116" at 10764.27,5570.91 h53.08 r45
  text "114" at 10867.01,5571.49 h53.08 r45
  text "110" at 11067.34,5571.49 h53.08 r45
  text "98" at 11671.3,5570.77 h53.08 r45
  text "88" at 12172.96,5570.77 h53.08 r45
  text "96" at 11769.96,5569.61 h53.08 r45
  text "94" at 11868.63,5570.19 h53.08 r45
  text "90" at 12071.53,5570.19 h53.08 r45
  text "86" at 12266.87,5569.61 h53.08 r45
  text "84" at 12368.53,5570.19 h53.08 r45
  text "80" at 12571.11,5570.19 h53.08 r45
  text "78" at 12671.73,5569.03 h53.08 r45
  text "76" at 12773.3,5567.87 h53.08 r45
  text "74" at 12873.87,5568.45 h53.08 r45
  text "VDD" at 8473.57,4642.61 h53.08 r270
  text "GND" at 8485.57,3808.61 h53.08
  text "AT32F457ZET7" at 11707.59,3757.38 h232.22
  text "42" at 11372.69,3453.66 h53.08 r45
  text "48" at 11673.41,3451.92 h53.08 r45
  text "40" at 11274.46,3451.34 h53.08 r45
  text "44" at 11469.84,3451.35 h53.08 r45
  text "46" at 11573.41,3450.77 h53.08 r45
  text "22" at 10368.8,3449.61 h53.08 r45
  text "62" at 12371.46,3449.03 h53.08 r45
  text "28" at 10669.28,3447.87 h53.08 r45
  text "32" at 10868.2,3448.45 h53.08 r45
  text "52" at 11870.12,3448.45 h53.08 r45
  text "20" at 10266.44,3447.3 h53.08 r45
  text "24" at 10469.59,3447.29 h53.08 r45
  text "26" at 10566.42,3446.72 h53.08 r45
  text "38" at 11173.03,3446.72 h53.08 r45
  text "58" at 12171.46,3446.72 h53.08 r45
  text "60" at 12270.46,3446.72 h53.08 r45
  text "64" at 12467.79,3446.72 h53.08 r45
  text "68" at 12666.79,3447.29 h53.08 r45
  text "72" at 12867.79,3447.3 h53.08 r45
  text "30" at 10770.34,3446.14 h53.08 r45
  text "34" at 10971.05,3446.14 h53.08 r45
  text "36" at 11070.17,3445.56 h53.08 r45
  text "50" at 11769.69,3446.14 h53.08 r45
  text "54" at 11973.12,3446.14 h53.08 r45
  text "56" at 12071.12,3445.56 h53.08 r45
  text "66" at 12566.79,3446.14 h53.08 r45
  text "70" at 12767.79,3444.98 h53.08 r45
  text "12" at 9860.93,3444.4 h53.08 r45
  text "18" at 10163.68,3442.67 h53.08 r45
  text "10" at 9760.53,3442.09 h53.08 r45
  text "14" at 9960.14,3442.09 h53.08 r45
  text "16" at 10058.56,3441.51 h53.08 r45
  text "4" at 9454.18,3439.81 h52.27 r45
  text "2" at 9353,3438.65 h52.27 r45
  text "6" at 9553.39,3435.76 h52.27 r45
  text "8" at 9655.36,3436.34 h52.27 r45
  text "43" at 11471.07,3178.79 h53.08 r45
  text "45" at 11568.21,3178.79 h53.08 r45
  text "49" at 11771.64,3178.21 h53.08 r45
  text "41" at 11365.35,3175.9 h53.08 r45
  text "23" at 10469.93,3174.74 h53.08 r45
  text "25" at 10569.08,3174.74 h53.08 r45
  text "47" at 11671.07,3175.32 h53.08 r45
  text "29" at 10766.57,3174.16 h53.08 r45
  text "33" at 10967.29,3173.58 h53.08 r45
  text "35" at 11069.12,3173.58 h53.08 r45
  text "53" at 11971.78,3173.58 h53.08 r45
  text "55" at 12067.78,3173.58 h53.08 r45
  text "63" at 12469.45,3174.16 h53.08 r45
  text "65" at 12576.45,3174.16 h53.08 r45
  text "69" at 12769.45,3173.58 h53.08 r45
  text "39" at 11272.12,3173 h53.08 r45
  text "59" at 12269.12,3173 h53.08 r45
  text "21" at 10363.71,3171.85 h53.08 r45
  text "27" at 10672.65,3171.27 h53.08 r45
  text "31" at 10863.71,3170.69 h53.08 r45
  text "51" at 11861.78,3170.69 h53.08 r45
  text "61" at 12366.12,3171.27 h53.08 r45
  text "67" at 12672.45,3170.69 h53.08 r45
  text "13" at 9961.34,3169.53 h53.08 r45
  text "15" at 10068.69,3169.53 h53.08 r45
  text "37" at 11167.83,3170.11 h53.08 r45
  text "57" at 12168.12,3170.11 h53.08 r45
  text "71" at 12864.45,3169.53 h53.08 r45
  text "19" at 10261.81,3168.96 h53.08 r45
  text "11" at 9858.98,3166.64 h53.08 r45
  text "17" at 10164.84,3166.06 h53.08 r45
  text "3" at 9457.35,3162.63 h52.27 r45
  text "5" at 9554.6,3162.63 h52.27 r45
  text "9" at 9752.63,3163.2 h52.27 r45
  text "1" at 9347.12,3160.89 h52.27 r45
  text "7" at 9655.39,3158 h52.27 r45
Mechanical Layer:
  circle w1: c12139.81,4865.97 r62.99
  circle w1: c10139.81,5465.96 r62.99
  circle w1: c10089.81,3565.97 r62.99
  circle w1: c8818.39,5874.63 r62.99
  circle w1: c8818.39,3158.09 r62.99
  circle w1: c13109.73,3158.09 r62.99
  circle w1: c13109.73,5874.63 r62.99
